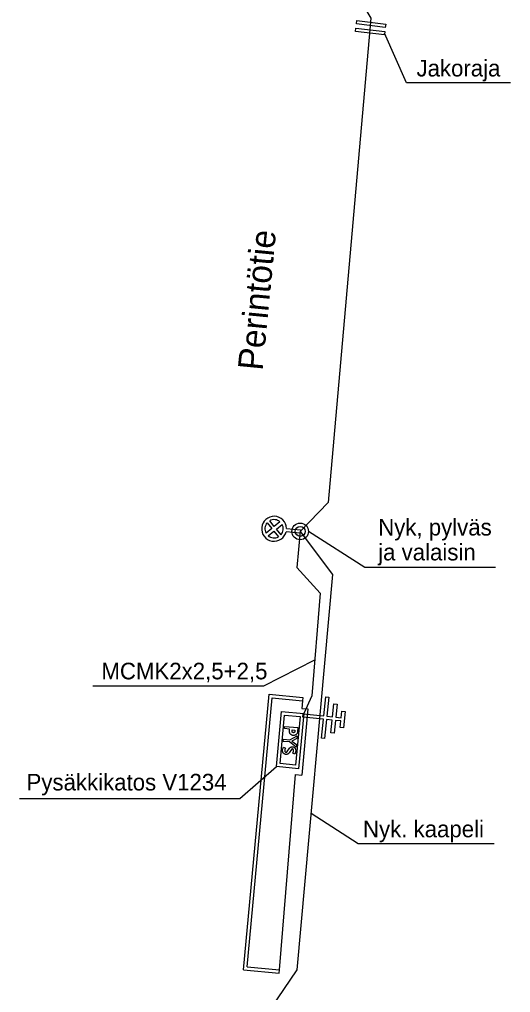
# Model space of a CAD drawing. Extents: x 25497852 to 25498297, y 6686544 to 6687252.
# Drawn here: x 25498228.7 to 25498273.1, y 6687062.7 to 6687150.6 of the extents above; entities that cross this region are included whole.
import ezdxf

# ---------------------------------------------------------------- set-up
doc = ezdxf.new("R2010")
doc.units = 0
for name, color, linetype in [('KayttoOikeusYksikko_piste_tunnus', 7, 'Continuous'), ('KiinteistoNimi', 7, 'Continuous'), ('Rajamerkki_tiealueenpaalu', 7, 'Continuous'), ('Rajamerkki_tonttipyykki', 7, 'Continuous'), ('Rajamerkki_yleisen_alueen_pyykki_ei_merkitty', 7, 'Continuous'), ('Rasitealue', 7, 'Continuous'), ('Rasiteviiva', 7, 'Continuous'), ('Taso 1', 7, 'Continuous')]:
    doc.layers.add(name, color=color, linetype=linetype)

msp = doc.modelspace()

# ---------------------------------------------------------------- linework, layer by layer
at = {"layer": 'KayttoOikeusYksikko_piste_tunnus'}
for p, q in [((25498251.085, 6687105.101), (25498251.503, 6687104.589)), ((25498251.736, 6687104.778), (25498251.318, 6687105.291)), ((25498252.248, 6687105.196), (25498251.736, 6687104.778)), ((25498251.925, 6687104.546), (25498252.438, 6687104.963)), ((25498251.503, 6687104.589), (25498250.99, 6687104.171)), ((25498251.18, 6687103.939), (25498251.693, 6687104.356)), ((25498251.693, 6687104.356), (25498252.11, 6687103.844)), ((25498252.343, 6687104.033), (25498251.925, 6687104.546)), ((25498254.057, 6687104.177), (25498252.808, 6687104.305)), ((25498252.839, 6687104.603), (25498254.087, 6687104.476)), ((25498254.087, 6687104.476), (25498254.057, 6687104.177))]:
    msp.add_line(p, q, dxfattribs=at)
for radius, start, end in [(1.125, 1.82875, 174.16649), (0.825, 139.64217, 174.16649), (0.825, 49.64217, 118.69081), (0.825, 354.16649, 28.69081), (1.125, 174.16649, 346.50424), (0.825, 174.16649, 208.69081), (0.825, 319.64217, 354.16649), (0.825, 229.64217, 298.69081)]:
    msp.add_arc((25498251.714, 6687104.567), radius, start, end, dxfattribs=at)
at = {"layer": 'KiinteistoNimi'}
for radius in [0.75, 0.45]:
    msp.add_circle((25498254.072, 6687104.332), radius, dxfattribs=at)
at = {"layer": 'Rajamerkki_tiealueenpaalu'}
for p, q in [((25498249.282, 6687064.992), (25498251.535, 6687089.288)), ((25498251.535, 6687089.288), (25498254.273, 6687089.032)), ((25498254.749, 6687088.289), (25498254.234, 6687082.306)), ((25498249.282, 6687064.992), (25498252.195, 6687064.727))]:
    msp.add_line(p, q, dxfattribs=at)
for points in [[(25498251.264, 6687089.614), (25498254.301, 6687089.333), (25498254.273, 6687089.032)], [(25498254.273, 6687089.032), (25498254.215, 6687088.339), (25498254.749, 6687088.289)], [(25498252.195, 6687064.727), (25498253.651, 6687082.36), (25498254.234, 6687082.306)], [(25498248.955, 6687064.721), (25498252.169, 6687064.423), (25498252.195, 6687064.727)]]:
    msp.add_lwpolyline(points, dxfattribs=at)
at = {"layer": 'Rajamerkki_tonttipyykki'}
for p, q in [((25498259.07, 6687149.496), (25498259.105, 6687149.793)), ((25498259.105, 6687149.793), (25498261.712, 6687149.484)), ((25498259.15, 6687150.172), (25498259.186, 6687150.47)), ((25498261.757, 6687149.863), (25498259.15, 6687150.172)), ((25498259.186, 6687150.47), (25498261.792, 6687150.16)), ((25498261.792, 6687150.16), (25498261.757, 6687149.863)), ((25498261.677, 6687149.186), (25498259.07, 6687149.496)), ((25498261.712, 6687149.484), (25498261.677, 6687149.186)), ((25498256.193, 6687087.669), (25498256.373, 6687089.384)), ((25498256.373, 6687089.384), (25498256.671, 6687089.353)), ((25498256.671, 6687089.353), (25498256.491, 6687087.637)), ((25498256.989, 6687087.585), (25498257.11, 6687088.741)), ((25498257.11, 6687088.741), (25498257.408, 6687088.71)), ((25498257.408, 6687088.71), (25498257.287, 6687087.554)), ((25498251.922, 6687083.08), (25498252.395, 6687088.058)), ((25498252.249, 6687083.351), (25498252.665, 6687087.731)), ((25498252.395, 6687088.058), (25498254.386, 6687087.869)), ((25498252.665, 6687087.731), (25498254.059, 6687087.599)), ((25498254.059, 6687087.599), (25498253.643, 6687083.218)), ((25498254.386, 6687087.869), (25498253.913, 6687082.891)), ((25498254.322, 6687087.563), (25498254.353, 6687087.861)), ((25498256.162, 6687087.37), (25498254.322, 6687087.563)), ((25498254.353, 6687087.861), (25498256.193, 6687087.669)), ((25498255.982, 6687085.655), (25498256.162, 6687087.37)), ((25498256.46, 6687087.339), (25498256.281, 6687085.623)), ((25498256.957, 6687087.287), (25498256.46, 6687087.339)), ((25498256.491, 6687087.637), (25498256.989, 6687087.585)), ((25498256.836, 6687086.131), (25498256.957, 6687087.287)), ((25498257.287, 6687087.554), (25498257.784, 6687087.502)), ((25498257.784, 6687087.502), (25498257.847, 6687088.099)), ((25498257.847, 6687088.099), (25498258.145, 6687088.068)), ((25498258.145, 6687088.068), (25498257.989, 6687086.576)), ((25498252.657, 6687086.517), (25498252.676, 6687086.716)), ((25498253.355, 6687086.4), (25498253.597, 6687086.377)), ((25498257.256, 6687087.256), (25498257.135, 6687086.1)), ((25498257.753, 6687087.204), (25498257.256, 6687087.256)), ((25498257.691, 6687086.607), (25498257.753, 6687087.204)), ((25498257.989, 6687086.576), (25498257.691, 6687086.607)), ((25498252.548, 6687085.364), (25498252.567, 6687085.563)), ((25498253.597, 6687086.377), (25498253.586, 6687086.259)), ((25498253.8, 6687085.864), (25498253.777, 6687085.626)), ((25498256.281, 6687085.623), (25498255.982, 6687085.655)), ((25498257.135, 6687086.1), (25498256.836, 6687086.131)), ((25498252.566, 6687084.851), (25498252.738, 6687084.75)), ((25498253.119, 6687084.749), (25498253.129, 6687084.761)), ((25498253.281, 6687084.63), (25498253.276, 6687084.624)), ((25498253.375, 6687084.878), (25498253.392, 6687084.876)), ((25498253.44, 6687084.646), (25498253.39, 6687084.678)), ((25498253.44, 6687084.646), (25498253.39, 6687084.678)), ((25498253.471, 6687084.562), (25498253.44, 6687084.646)), ((25498253.471, 6687084.562), (25498253.44, 6687084.646)), ((25498253.606, 6687084.744), (25498253.617, 6687084.731)), ((25498253.725, 6687085.075), (25498253.702, 6687084.837)), ((25498252.469, 6687084.538), (25498252.473, 6687084.549)), ((25498252.585, 6687084.269), (25498252.58, 6687084.273)), ((25498252.671, 6687084.514), (25498252.671, 6687084.498)), ((25498252.707, 6687084.429), (25498252.713, 6687084.422)), ((25498252.804, 6687084.385), (25498252.811, 6687084.385)), ((25498252.816, 6687084.185), (25498252.809, 6687084.184)), ((25498252.892, 6687084.425), (25498252.899, 6687084.437)), ((25498253.063, 6687084.322), (25498253.066, 6687084.326)), ((25498253.576, 6687084.211), (25498253.4, 6687084.307)), ((25498253.473, 6687084.534), (25498253.471, 6687084.562)), ((25498253.473, 6687084.534), (25498253.471, 6687084.562)), ((25498253.669, 6687084.518), (25498253.669, 6687084.492)), ((25498253.913, 6687082.891), (25498251.922, 6687083.08)), ((25498253.643, 6687083.218), (25498252.249, 6687083.351))]:
    msp.add_line(p, q, dxfattribs=at)
for points in [[(25498253.111, 6687086.473), (25498252.657, 6687086.517)], [(25498252.676, 6687086.716), (25498253.87, 6687086.602), (25498253.834, 6687086.228)], [(25498253.094, 6687086.299), (25498253.111, 6687086.473)], [(25498253.343, 6687086.275), (25498253.355, 6687086.4)], [(25498252.567, 6687085.563), (25498253.13, 6687085.51), (25498253.8, 6687085.864)], [(25498253.834, 6687086.222), (25498253.828, 6687086.189), (25498253.818, 6687086.151), (25498253.804, 6687086.115), (25498253.786, 6687086.081), (25498253.765, 6687086.048), (25498253.74, 6687086.018), (25498253.713, 6687085.991), (25498253.682, 6687085.967), (25498253.65, 6687085.946), (25498253.615, 6687085.928), (25498253.579, 6687085.915), (25498253.541, 6687085.905), (25498253.503, 6687085.899), (25498253.464, 6687085.897), (25498253.426, 6687085.899), (25498253.387, 6687085.906), (25498253.35, 6687085.916), (25498253.314, 6687085.93), (25498253.279, 6687085.948), (25498253.247, 6687085.969), (25498253.217, 6687085.994), (25498253.19, 6687086.021), (25498253.165, 6687086.052), (25498253.144, 6687086.084), (25498253.127, 6687086.119), (25498253.113, 6687086.155), (25498253.104, 6687086.193), (25498253.098, 6687086.231), (25498253.096, 6687086.269), (25498253.094, 6687086.299)], [(25498253.778, 6687085.626), (25498253.331, 6687085.39)], [(25498253.586, 6687086.259), (25498253.584, 6687086.242), (25498253.58, 6687086.23), (25498253.576, 6687086.218), (25498253.57, 6687086.207), (25498253.563, 6687086.197), (25498253.555, 6687086.187), (25498253.546, 6687086.178), (25498253.536, 6687086.17), (25498253.526, 6687086.163), (25498253.515, 6687086.158), (25498253.502, 6687086.153), (25498253.491, 6687086.15), (25498253.478, 6687086.148), (25498253.465, 6687086.148), (25498253.453, 6687086.148), (25498253.441, 6687086.15), (25498253.429, 6687086.154), (25498253.417, 6687086.158), (25498253.406, 6687086.164), (25498253.395, 6687086.171), (25498253.385, 6687086.179), (25498253.377, 6687086.188), (25498253.369, 6687086.198), (25498253.362, 6687086.208), (25498253.356, 6687086.219), (25498253.352, 6687086.231), (25498253.349, 6687086.243), (25498253.346, 6687086.256), (25498253.344, 6687086.267), (25498253.343, 6687086.275)], [(25498252.473, 6687084.549), (25498252.481, 6687084.614), (25498252.498, 6687084.689), (25498252.522, 6687084.762), (25498252.554, 6687084.833), (25498252.566, 6687084.851)], [(25498252.473, 6687084.549), (25498252.481, 6687084.614), (25498252.498, 6687084.689), (25498252.522, 6687084.762), (25498252.554, 6687084.833), (25498252.566, 6687084.851)], [(25498253.111, 6687085.311), (25498252.548, 6687085.364)], [(25498252.738, 6687084.75), (25498252.732, 6687084.74), (25498252.709, 6687084.689), (25498252.691, 6687084.636), (25498252.679, 6687084.581), (25498252.671, 6687084.514)], [(25498252.738, 6687084.75), (25498252.732, 6687084.74), (25498252.709, 6687084.689), (25498252.691, 6687084.636), (25498252.679, 6687084.581), (25498252.671, 6687084.514)], [(25498252.899, 6687084.437), (25498253.119, 6687084.749)], [(25498252.899, 6687084.437), (25498253.119, 6687084.749)], [(25498253.702, 6687084.837), (25498253.111, 6687085.311)], [(25498253.129, 6687084.761), (25498253.151, 6687084.783), (25498253.179, 6687084.807), (25498253.21, 6687084.828), (25498253.243, 6687084.845), (25498253.277, 6687084.859), (25498253.313, 6687084.869), (25498253.349, 6687084.876), (25498253.375, 6687084.878)], [(25498253.129, 6687084.761), (25498253.151, 6687084.783), (25498253.179, 6687084.807), (25498253.21, 6687084.828), (25498253.243, 6687084.845), (25498253.277, 6687084.859), (25498253.313, 6687084.869), (25498253.349, 6687084.876), (25498253.375, 6687084.878)], [(25498253.39, 6687084.678), (25498253.374, 6687084.677), (25498253.358, 6687084.674), (25498253.342, 6687084.67), (25498253.327, 6687084.664), (25498253.313, 6687084.656), (25498253.3, 6687084.647), (25498253.287, 6687084.637), (25498253.281, 6687084.63)], [(25498253.39, 6687084.678), (25498253.374, 6687084.677), (25498253.358, 6687084.674), (25498253.342, 6687084.67), (25498253.327, 6687084.664), (25498253.313, 6687084.656), (25498253.3, 6687084.647), (25498253.287, 6687084.637), (25498253.281, 6687084.63)], [(25498253.331, 6687085.39), (25498253.725, 6687085.075)], [(25498253.392, 6687084.876), (25498253.415, 6687084.874), (25498253.443, 6687084.868), (25498253.469, 6687084.86), (25498253.495, 6687084.849), (25498253.52, 6687084.835), (25498253.542, 6687084.818), (25498253.563, 6687084.8), (25498253.582, 6687084.779), (25498253.598, 6687084.757), (25498253.606, 6687084.744)], [(25498253.392, 6687084.876), (25498253.415, 6687084.874), (25498253.443, 6687084.868), (25498253.469, 6687084.86), (25498253.495, 6687084.849), (25498253.52, 6687084.835), (25498253.542, 6687084.818), (25498253.563, 6687084.8), (25498253.582, 6687084.779), (25498253.598, 6687084.757), (25498253.606, 6687084.744)], [(25498253.617, 6687084.731), (25498253.637, 6687084.684), (25498253.653, 6687084.63), (25498253.664, 6687084.576), (25498253.669, 6687084.523), (25498253.669, 6687084.518)], [(25498253.617, 6687084.731), (25498253.637, 6687084.684), (25498253.653, 6687084.63), (25498253.664, 6687084.576), (25498253.669, 6687084.523), (25498253.669, 6687084.518)], [(25498252.58, 6687084.273), (25498252.566, 6687084.286), (25498252.543, 6687084.312), (25498252.522, 6687084.341), (25498252.505, 6687084.371), (25498252.49, 6687084.404), (25498252.479, 6687084.438), (25498252.472, 6687084.472), (25498252.469, 6687084.508), (25498252.469, 6687084.538)], [(25498252.58, 6687084.273), (25498252.566, 6687084.286), (25498252.543, 6687084.312), (25498252.522, 6687084.341), (25498252.505, 6687084.371), (25498252.49, 6687084.404), (25498252.479, 6687084.438), (25498252.472, 6687084.472), (25498252.469, 6687084.508), (25498252.469, 6687084.538)], [(25498252.809, 6687084.184), (25498252.788, 6687084.186), (25498252.751, 6687084.19), (25498252.714, 6687084.199), (25498252.678, 6687084.212), (25498252.644, 6687084.229), (25498252.611, 6687084.249), (25498252.585, 6687084.269)], [(25498252.809, 6687084.184), (25498252.788, 6687084.186), (25498252.751, 6687084.19), (25498252.714, 6687084.199), (25498252.678, 6687084.212), (25498252.644, 6687084.229), (25498252.611, 6687084.249), (25498252.585, 6687084.269)], [(25498252.671, 6687084.498), (25498252.673, 6687084.488), (25498252.678, 6687084.475), (25498252.683, 6687084.462), (25498252.691, 6687084.449), (25498252.699, 6687084.437), (25498252.707, 6687084.429)], [(25498252.671, 6687084.498), (25498252.673, 6687084.488), (25498252.678, 6687084.475), (25498252.683, 6687084.462), (25498252.691, 6687084.449), (25498252.699, 6687084.437), (25498252.707, 6687084.429)], [(25498252.713, 6687084.422), (25498252.725, 6687084.414), (25498252.739, 6687084.405), (25498252.755, 6687084.397), (25498252.772, 6687084.391), (25498252.788, 6687084.387), (25498252.804, 6687084.385)], [(25498252.713, 6687084.422), (25498252.725, 6687084.414), (25498252.739, 6687084.405), (25498252.755, 6687084.397), (25498252.772, 6687084.391), (25498252.788, 6687084.387), (25498252.804, 6687084.385)], [(25498252.811, 6687084.385), (25498252.826, 6687084.385), (25498252.835, 6687084.386), (25498252.843, 6687084.388), (25498252.852, 6687084.391), (25498252.86, 6687084.395), (25498252.868, 6687084.4), (25498252.875, 6687084.405), (25498252.882, 6687084.412), (25498252.888, 6687084.419), (25498252.892, 6687084.425)], [(25498252.811, 6687084.385), (25498252.826, 6687084.385), (25498252.835, 6687084.386), (25498252.843, 6687084.388), (25498252.852, 6687084.391), (25498252.86, 6687084.395), (25498252.868, 6687084.4), (25498252.875, 6687084.405), (25498252.882, 6687084.412), (25498252.888, 6687084.419), (25498252.892, 6687084.425)], [(25498253.066, 6687084.326), (25498253.063, 6687084.32), (25498253.046, 6687084.296), (25498253.027, 6687084.273), (25498253.005, 6687084.253), (25498252.981, 6687084.235), (25498252.955, 6687084.219), (25498252.928, 6687084.206), (25498252.9, 6687084.196), (25498252.871, 6687084.189), (25498252.841, 6687084.185), (25498252.816, 6687084.185)], [(25498253.066, 6687084.326), (25498253.063, 6687084.32), (25498253.046, 6687084.296), (25498253.027, 6687084.273), (25498253.005, 6687084.253), (25498252.981, 6687084.235), (25498252.955, 6687084.219), (25498252.928, 6687084.206), (25498252.9, 6687084.196), (25498252.871, 6687084.189), (25498252.841, 6687084.185), (25498252.816, 6687084.185)], [(25498253.276, 6687084.624), (25498253.063, 6687084.322)], [(25498253.276, 6687084.624), (25498253.063, 6687084.322)], [(25498253.4, 6687084.307), (25498253.43, 6687084.374), (25498253.455, 6687084.451), (25498253.473, 6687084.534)], [(25498253.4, 6687084.307), (25498253.43, 6687084.374), (25498253.455, 6687084.451), (25498253.473, 6687084.534)], [(25498253.669, 6687084.492), (25498253.649, 6687084.398), (25498253.617, 6687084.302), (25498253.576, 6687084.211)], [(25498253.669, 6687084.492), (25498253.649, 6687084.398), (25498253.617, 6687084.302), (25498253.576, 6687084.211)]]:
    msp.add_lwpolyline(points, dxfattribs=at)
at = {"layer": 'Rajamerkki_yleisen_alueen_pyykki_ei_merkitty'}
msp.add_line((25498248.955, 6687064.721), (25498251.264, 6687089.614), dxfattribs=at)
at = {"layer": 'Rasitealue'}
for points in [[(25498258.332, 6687154.238), (25498260.462, 6687150.684), (25498256.587, 6687106.941), (25498254.072, 6687104.332)], [(25498254.072, 6687104.332), (25498257.002, 6687100.447), (25498253.772, 6687064.73), (25498250.221, 6687059.486)], [(25498254.072, 6687104.332), (25498253.775, 6687101.078), (25498255.878, 6687098.752), (25498255.138, 6687089.468), (25498254.386, 6687087.869)]]:
    msp.add_lwpolyline(points, dxfattribs=at)
at = {"layer": 'Taso 1'}
for points in [[(25498273.066, 6687144.846), (25498263.681, 6687144.846), (25498261.694, 6687149.335)], [(25498271.716, 6687101.064), (25498259.91, 6687101.064), (25498254.822, 6687104.332)], [(25498235.35, 6687090.392), (25498250.774, 6687090.392), (25498255.399, 6687092.732)], [(25498228.722, 6687080.196), (25498248.636, 6687080.196), (25498251.922, 6687083.08)], [(25498271.583, 6687076.121), (25498259.32, 6687076.121), (25498255.065, 6687078.854)]]:
    msp.add_lwpolyline(points, dxfattribs=at)

# ---------------------------------------------------------------- texts
at = {"layer": 'Rasiteviiva'}
for s, p in [('Jakoraja', (25498264.574, 6687145.424)), ('Nyk, pylväs', (25498261.114, 6687103.958)), ('ja valaisin', (25498261.114, 6687101.708)), ('MCMK2x2,5+2,5', (25498236.122, 6687090.966)), ('Pysäkkikatos V1234', (25498229.361, 6687080.929)), ('Nyk. kaapeli', (25498259.742, 6687076.698))]:
    msp.add_text(s, height=1.5, dxfattribs=at).set_placement(p)
msp.add_text('Perintötie', height=2.25, rotation=84.47275, dxfattribs=at).set_placement((25498250.674, 6687118.811))

doc.saveas('drawing.dxf')
